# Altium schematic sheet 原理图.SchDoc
size A4
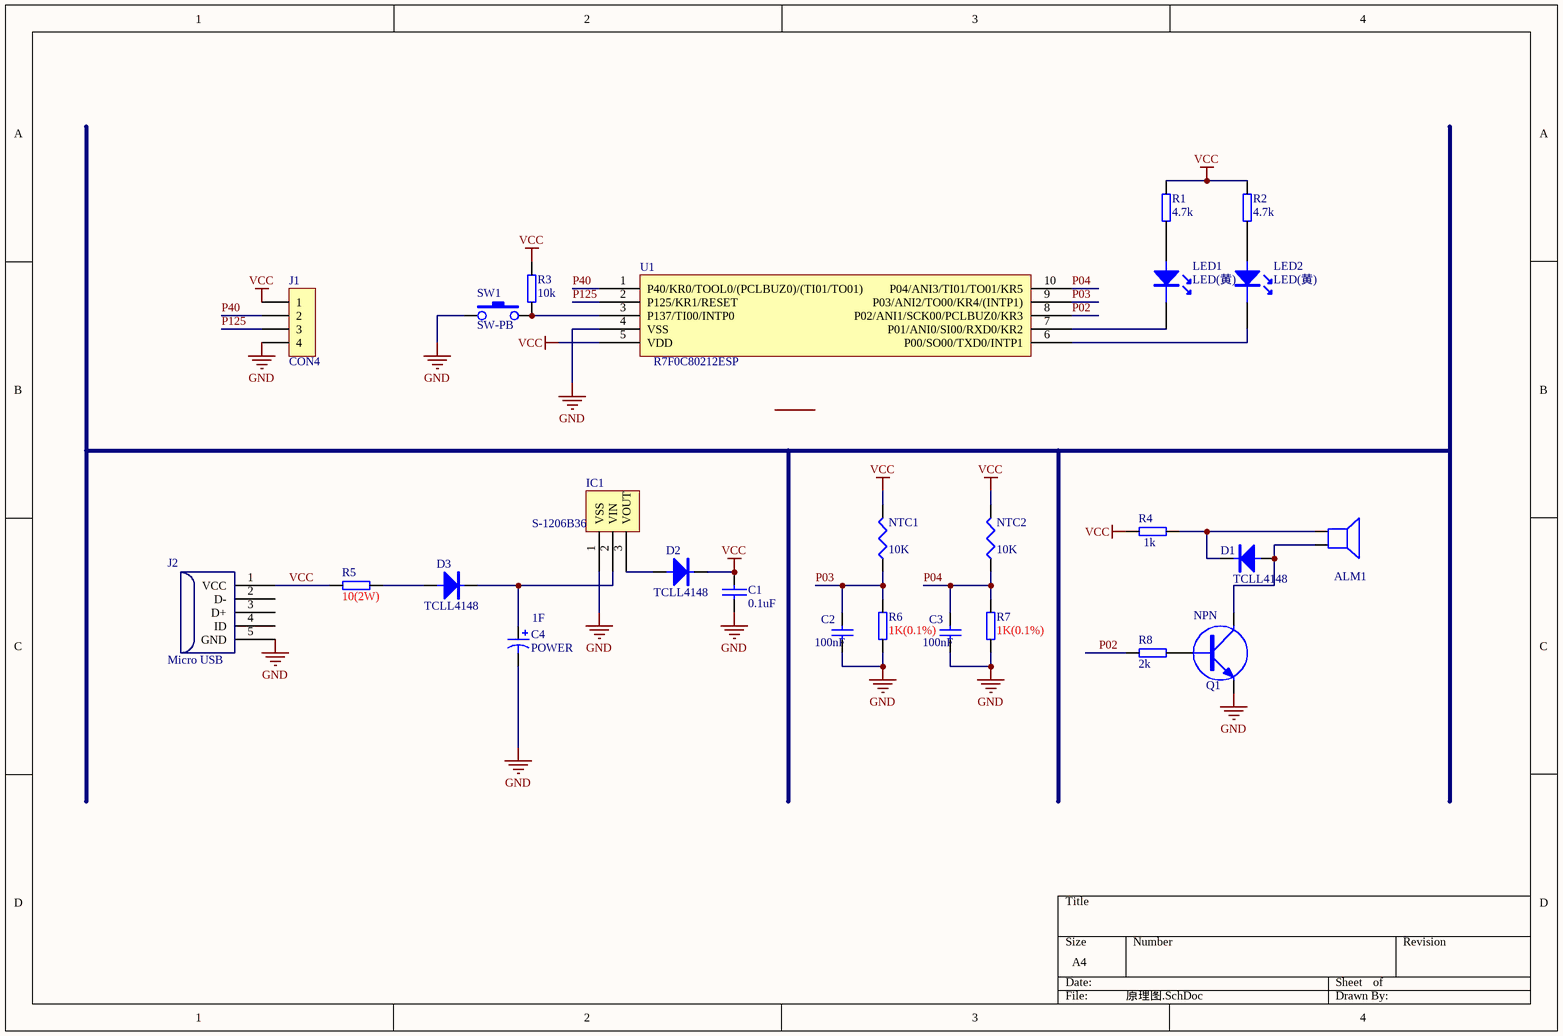
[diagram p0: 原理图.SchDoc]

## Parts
ALM1  (no value)  [BEEN]
C1  0.1uF  [0603C]
C2  100nF  [0603C]
C3  100nF  [0603C]
C4  POWER  value 1F  [CPOWER]
D1  TCLL4148  [3216]
D2  TCLL4148  [3216]
D3  TCLL4148  [3216]
IC1  S-1206B36  [SOT-89]
J1  CON4  [SIP4]
J2  Micro USB  [Mini usb]
LED1  LED(黄)  [LED0603]
LED2  LED(黄)  [LED0603]
NTC1  value 10K  [NTC]  (hidden comment: Res3)
NTC2  value 10K  [NTC]  (hidden comment: Res3)
Q1  NPN  [SOT-23A]
R1  4.7k  [0603]
R2  4.7k  [0603]
R3  10k  [0603]
R4  1k  [0603]
R5  10(2W)  [AXIAL0.4]
R6  1K(0.1%)  [0603]
R7  1K(0.1%)  [0603]
R8  2k  [0603]
SW1  SW-PB  [SKEY]
U1  R7F0C80212ESP  [SOP127P600-8N]

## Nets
GND: C1.2 C2.1 C3.1 C4.2 IC1.1(VSS) J1.4 J2.5(GND) Q1.2(E) R6.1 R7.1 SW1.1 U1.4(VSS)
VCC: C1.1 D2.2(K) J1.1 J2.1(VCC) NTC1.2 NTC2.2 R1.1 R2.1 R3.1 R4.1 R5.2 U1.5(VDD)
P02: R8.2 U1.8(P02/ANI1/SCK00/PCLBUZ0/KR3)
P03: C2.2 NTC1.1 R6.2 U1.9(P03/ANI2/TO00/KR4/(INTP1))
P04: C3.2 NTC2.1 R7.2 U1.10(P04/ANI3/TI01/TO01/KR5)
P40: J1.2 U1.1(P40/KR0/TOOL0/(PCLBUZ0)/(TI01/TO01))
P125: J1.3 U1.2(P125/KR1/RESET)
NetALM1_1: ALM1.1 D1.2(K) R4.2
NetALM1_2: ALM1.2 D1.1(A) Q1.3(C)
NetC4_1: C4.1 D3.2(K) IC1.2(VIN)
NetD2_1: D2.1(A) IC1.3(VOUT)
NetD3_1: D3.1(A) R5.1
NetLED1_1: LED1.1(A) R1.2
NetLED1_2: LED1.2(K) U1.7(P01/ANI0/SI00/RXD0/KR2)
NetLED2_1: LED2.1(A) R2.2
NetLED2_2: LED2.2(K) U1.6(P00/SO00/TXD0/INTP1)
NetQ1_1: Q1.1(B) R8.1
NetR3_2: R3.2 SW1.2 U1.3(P137/TI00/INTP0)

Not connected (* = marked no-connect by the designer): J2 2(D-) 3(D+) 4(ID)

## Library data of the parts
ALM1 = SPEAKER
C1 = CAP: Capacitor
C2 C3 = Cap: Capacitor; Manufacturer: Generic Components; Class: Passive; Value: 100pF
C4 = Cap Pol1: Polarized Capacitor (Radial)
D1-D3 = DIODE
IC1 = CON3: Connector
J1 = CO: Connector
J2 = M
LED1 LED2 = LED
NTC1 NTC2 = Res3: Resistor
Q1 = NPN: NPN  Transistor BC817(SOT-23)
R1-R3 R8 = RES2
R4-R7 = RESX
SW1 = S: Switch
U1 = R7F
